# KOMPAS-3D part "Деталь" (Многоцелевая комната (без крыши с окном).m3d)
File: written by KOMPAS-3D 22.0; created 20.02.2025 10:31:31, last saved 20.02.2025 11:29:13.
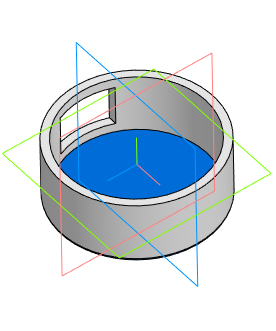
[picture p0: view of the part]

Document properties: Автор: Пользователь Windows; Полное имя файла: C:\Users\Student\Documents\Картошечка\База Сабнатика\Многоцелевая комната (без крыши с окном).m3d

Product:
- Part/product: Деталь
    Масса: 0.109336

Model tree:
1. Эскиз:3
2. Элемент вращения:1
     Угол 1 = 360
3. Скругление:1  (with: Элемент вращения:1)
     Радиус = 1
4. Эскиз:4  (with: Элемент вращения:1)
5. Элемент выдавливания:1
     Расстояние 2 = 6.1
6. Эскиз:5  (with: Элемент выдавливания:1)
7. Элемент выдавливания:2
     Расстояние 2 = 19
8. Эскиз:6
9. Элемент выдавливания:3
     Расстояние 2 = 25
